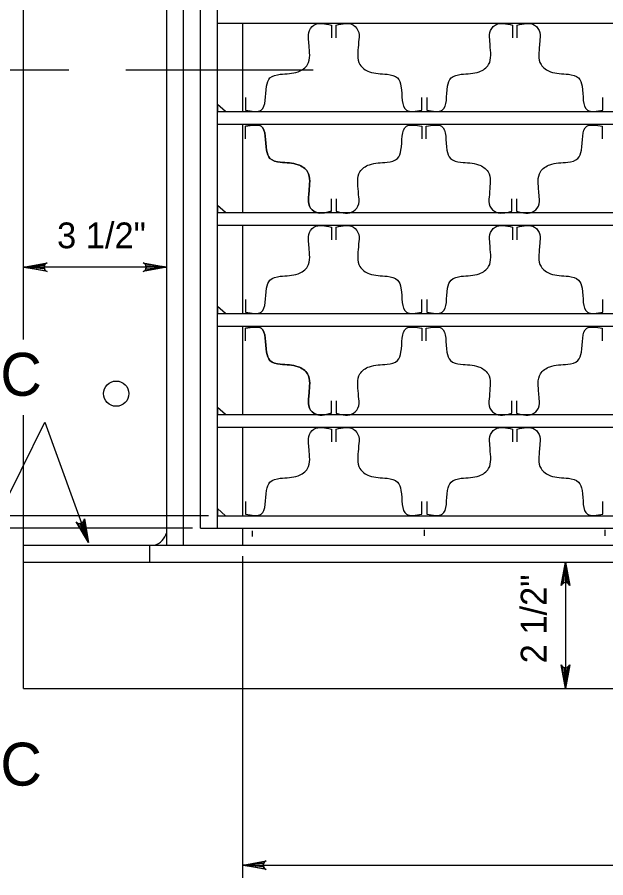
# Model space of a CAD drawing. Extents: x 0.71 to 8.05, y -5.67 to 4.31.
# Drawn here: x 2.185 to 3.555, y 0.105 to 2.109 of the extents above; entities that cross this region are included whole.
import ezdxf

# ---------------------------------------------------------------- set-up
doc = ezdxf.new("R2010")
doc.units = 0
for name, color, linetype in [('DETL-DIMS', 7, 'Continuous'), ('DETL-LINE', 7, 'Continuous'), ('DETL-NOTE', 7, 'Continuous'), ('DETL-TITL', 7, 'Continuous')]:
    doc.layers.add(name, color=color, linetype=linetype)

msp = doc.modelspace()

# ---------------------------------------------------------------- linework, layer by layer
at = {"layer": 'DETL-DIMS'}
for p, q in [((2.0816, 1.9865), (2.3051, 1.9865)), ((2.4374, 1.9865), (2.874, 1.9865)), ((2.5328, 1.527), (2.1992, 1.527)), ((1.8636, 0.3868), (2.2488, 1.1658)), ((2.2488, 1.1658), (2.3502, 0.8858)), ((2.6302, 0.9483), (1.9345, 0.9483)), ((2.5928, 0.9189), (1.7286, 0.9189)), ((2.7098, 0.1048), (2.7098, 0.854)), ((3.4615, 0.8401), (3.4615, 0.546)), ((2.7098, 0.1342), (6.5122, 0.1342))]:
    msp.add_line(p, q, dxfattribs=at)
for points in [[(2.1992, 1.527), (2.2541, 1.5373), (2.2498, 1.5344), (2.2477, 1.5307), (2.247, 1.527), (2.2477, 1.5234), (2.2498, 1.5197), (2.2541, 1.5168), (2.1992, 1.527), (2.2498, 1.5197), (2.2477, 1.5234), (2.1992, 1.527), (2.247, 1.527), (2.2477, 1.5307), (2.1992, 1.527), (2.2498, 1.5344)], [(2.5328, 1.527), (2.4779, 1.5168), (2.4822, 1.5197), (2.4843, 1.5234), (2.485, 1.527), (2.4843, 1.5307), (2.4822, 1.5344), (2.4779, 1.5373), (2.5328, 1.527), (2.4822, 1.5344), (2.4843, 1.5307), (2.5328, 1.527), (2.485, 1.527), (2.4843, 1.5234), (2.5328, 1.527), (2.4822, 1.5197)], [(2.3502, 0.8858), (2.3218, 0.9339), (2.326, 0.9309), (2.3302, 0.9301), (2.3339, 0.9308), (2.3371, 0.9326), (2.3399, 0.9359), (2.3412, 0.9409), (2.3502, 0.8858), (2.3399, 0.9359), (2.3371, 0.9326), (2.3502, 0.8858), (2.3339, 0.9308), (2.3302, 0.9301), (2.3502, 0.8858), (2.326, 0.9309)], [(3.4615, 0.8401), (3.4718, 0.7853), (3.4689, 0.7895), (3.4652, 0.7917), (3.4615, 0.7923), (3.4578, 0.7917), (3.4542, 0.7895), (3.4512, 0.7853), (3.4615, 0.8401), (3.4542, 0.7895), (3.4578, 0.7917), (3.4615, 0.8401), (3.4615, 0.7923), (3.4652, 0.7917), (3.4615, 0.8401), (3.4689, 0.7895)], [(3.4615, 0.546), (3.4512, 0.6008), (3.4542, 0.5966), (3.4578, 0.5944), (3.4615, 0.5938), (3.4652, 0.5944), (3.4689, 0.5966), (3.4718, 0.6008), (3.4615, 0.546), (3.4689, 0.5966), (3.4652, 0.5944), (3.4615, 0.546), (3.4615, 0.5938), (3.4578, 0.5944), (3.4615, 0.546), (3.4542, 0.5966)], [(2.7098, 0.1342), (2.7646, 0.1445), (2.7604, 0.1416), (2.7582, 0.1379), (2.7576, 0.1342), (2.7582, 0.1305), (2.7604, 0.1268), (2.7646, 0.1239), (2.7098, 0.1342), (2.7604, 0.1268), (2.7582, 0.1305), (2.7098, 0.1342), (2.7576, 0.1342), (2.7582, 0.1379), (2.7098, 0.1342), (2.7604, 0.1416)]]:
    msp.add_lwpolyline(points, dxfattribs=at)
at = {"layer": 'DETL-LINE'}
for p, q in [((2.1992, 1.3586), (2.1992, 3.2036)), ((2.5328, 0.8795), (2.5328, 2.8701)), ((2.5722, 0.8795), (2.5722, 2.8701)), ((2.6116, 0.9189), (2.6116, 2.8307)), ((2.651, 0.9189), (2.651, 2.8307)), ((2.651, 2.0954), (6.571, 2.0954)), ((2.7098, 1.8895), (2.7098, 2.0954)), ((2.9162, 2.0909), (2.9162, 2.0615)), ((2.9274, 2.0615), (2.9274, 2.0909)), ((3.338, 2.0909), (3.338, 2.0615)), ((3.3492, 2.0615), (3.3492, 2.0909)), ((2.7166, 1.9223), (2.7166, 1.8928)), ((3.127, 1.8928), (3.127, 1.9223)), ((3.1384, 1.9223), (3.1384, 1.8928)), ((3.5488, 1.8928), (3.5488, 1.9223)), ((2.651, 1.8895), (6.571, 1.8895)), ((2.651, 1.8601), (6.571, 1.8601)), ((2.7098, 1.6542), (2.7098, 1.8601)), ((2.7166, 1.8259), (2.7166, 1.8554)), ((3.127, 1.8554), (3.127, 1.8259)), ((3.1369, 1.8259), (3.1369, 1.8554)), ((3.5473, 1.8554), (3.5473, 1.8259)), ((2.9162, 1.6573), (2.9162, 1.6867)), ((2.9274, 1.6867), (2.9274, 1.6573)), ((3.3365, 1.6573), (3.3365, 1.6867)), ((3.3477, 1.6867), (3.3477, 1.6573)), ((2.651, 1.6542), (6.571, 1.6542)), ((2.651, 1.6248), (6.571, 1.6248)), ((2.7098, 1.4189), (2.7098, 1.6248)), ((2.9162, 1.6203), (2.9162, 1.5909)), ((2.9274, 1.5909), (2.9274, 1.6203)), ((3.338, 1.6203), (3.338, 1.5909)), ((3.3492, 1.5909), (3.3492, 1.6203)), ((2.7166, 1.4517), (2.7166, 1.4222)), ((3.127, 1.4222), (3.127, 1.4517)), ((3.1384, 1.4517), (3.1384, 1.4222)), ((3.5488, 1.4222), (3.5488, 1.4517)), ((2.651, 1.4189), (6.571, 1.4189)), ((2.651, 1.3895), (6.571, 1.3895)), ((2.7098, 1.1836), (2.7098, 1.3895)), ((2.7166, 1.3553), (2.7166, 1.3848)), ((3.127, 1.3848), (3.127, 1.3553)), ((3.1369, 1.3553), (3.1369, 1.3848)), ((3.5473, 1.3848), (3.5473, 1.3553)), ((2.9162, 1.1867), (2.9162, 1.2161)), ((2.9274, 1.2161), (2.9274, 1.1867)), ((3.3365, 1.1867), (3.3365, 1.2161)), ((3.3477, 1.2161), (3.3477, 1.1867)), ((2.651, 1.1836), (6.571, 1.1836)), ((2.1992, 0.546), (2.1992, 1.1826)), ((2.651, 1.1542), (6.571, 1.1542)), ((2.7098, 0.9483), (2.7098, 1.1542)), ((2.9162, 1.1497), (2.9162, 1.1203)), ((2.9274, 1.1203), (2.9274, 1.1497)), ((3.338, 1.1497), (3.338, 1.1203)), ((3.3492, 1.1203), (3.3492, 1.1497)), ((2.7166, 0.9811), (2.7166, 0.9517)), ((3.127, 0.9517), (3.127, 0.9811)), ((3.1384, 0.9811), (3.1384, 0.9517)), ((3.5488, 0.9517), (3.5488, 0.9811)), ((2.651, 0.9483), (6.571, 0.9483)), ((2.6116, 0.9189), (6.6104, 0.9189)), ((2.7098, 0.8795), (2.7098, 0.9189)), ((2.7327, 0.8996), (2.7327, 0.9132)), ((3.1331, 0.9017), (3.1331, 0.9154)), ((3.5537, 0.9017), (3.5537, 0.9154)), ((2.1992, 0.8795), (7.0228, 0.8795)), ((2.4933, 0.8401), (2.4933, 0.8795)), ((2.1992, 0.8401), (7.0228, 0.8401)), ((2.1992, 0.546), (7.0228, 0.546))]:
    msp.add_line(p, q, dxfattribs=at)
for points in [[(2.6695, 1.8895), (2.651, 1.9059), (2.651, 1.8895)], [(2.6695, 1.6542), (2.651, 1.6706), (2.651, 1.6542)], [(2.6695, 1.4189), (2.651, 1.4353), (2.651, 1.4189)], [(2.6695, 1.1836), (2.651, 1.2), (2.651, 1.1836)], [(2.6695, 0.9483), (2.651, 0.9647), (2.651, 0.9483)]]:
    msp.add_lwpolyline(points, close=True, dxfattribs=at)
msp.add_circle((2.4151, 1.2325), 0.0294, dxfattribs=at)
msp.add_arc((2.4933, 0.9189), 0.0407, 284.2782, 345.7218, dxfattribs=at)
for points in [[(2.7166, 1.8928), (2.7526, 1.8928), (2.7652, 1.9485), (2.7733, 1.9678), (2.7971, 1.9765), (2.8389, 1.9824), (2.8608, 1.999), (2.8643, 2.0445), (2.8639, 2.0521), (2.8634, 2.0736), (2.8758, 2.0909), (2.9162, 2.0909)], [(2.9274, 2.0909), (2.9678, 2.0909), (2.9801, 2.0736), (2.9797, 2.0521), (2.9792, 2.0445), (2.9828, 1.999), (3.0047, 1.9824), (3.0465, 1.9765), (3.0703, 1.9678), (3.0784, 1.9485), (3.091, 1.8928), (3.127, 1.8928)], [(3.1384, 1.8928), (3.1744, 1.8928), (3.187, 1.9485), (3.1951, 1.9678), (3.2189, 1.9765), (3.2607, 1.9824), (3.2826, 1.999), (3.2861, 2.0445), (3.2857, 2.0521), (3.2852, 2.0736), (3.2976, 2.0909), (3.338, 2.0909)], [(3.3492, 2.0909), (3.3896, 2.0909), (3.4019, 2.0736), (3.4015, 2.0521), (3.401, 2.0445), (3.4046, 1.999), (3.4265, 1.9824), (3.4683, 1.9765), (3.4921, 1.9678), (3.5002, 1.9485), (3.5128, 1.8928), (3.5488, 1.8928)], [(2.7166, 1.8554), (2.7526, 1.8554), (2.7652, 1.7997), (2.7733, 1.7804), (2.7971, 1.7717), (2.8389, 1.7658), (2.8608, 1.7492), (2.8643, 1.7037), (2.8639, 1.696), (2.8634, 1.6746), (2.8758, 1.6573), (2.9162, 1.6573)], [(2.7166, 1.8554), (2.7526, 1.8554), (2.7652, 1.7997), (2.7733, 1.7804), (2.7971, 1.7717), (2.8389, 1.7658), (2.8608, 1.7492), (2.8643, 1.7037), (2.8639, 1.696), (2.8634, 1.6746), (2.8758, 1.6573), (2.9162, 1.6573)], [(2.9162, 1.6573), (2.8758, 1.6573), (2.8634, 1.6746), (2.8639, 1.696), (2.8643, 1.7037), (2.8608, 1.7492), (2.8389, 1.7658), (2.7971, 1.7717), (2.7733, 1.7804), (2.7652, 1.7997), (2.7526, 1.8554), (2.7166, 1.8554)], [(2.7166, 1.8554), (2.7526, 1.8554), (2.7652, 1.7997), (2.7733, 1.7804), (2.7971, 1.7717), (2.8389, 1.7658), (2.8608, 1.7492), (2.8643, 1.7037), (2.8639, 1.696), (2.8634, 1.6746), (2.8758, 1.6573), (2.9162, 1.6573)], [(2.7166, 1.8554), (2.7526, 1.8554), (2.7652, 1.7997), (2.7733, 1.7804), (2.7971, 1.7717), (2.8389, 1.7658), (2.8608, 1.7492), (2.8643, 1.7037), (2.8639, 1.696), (2.8634, 1.6746), (2.8758, 1.6573), (2.9162, 1.6573)], [(2.9274, 1.6573), (2.9678, 1.6573), (2.9801, 1.6746), (2.9797, 1.696), (2.9792, 1.7037), (2.9828, 1.7492), (3.0047, 1.7658), (3.0465, 1.7717), (3.0703, 1.7804), (3.0784, 1.7997), (3.091, 1.8554), (3.127, 1.8554)], [(2.9274, 1.6573), (2.9678, 1.6573), (2.9801, 1.6746), (2.9797, 1.696), (2.9792, 1.7037), (2.9828, 1.7492), (3.0047, 1.7658), (3.0465, 1.7717), (3.0703, 1.7804), (3.0784, 1.7997), (3.091, 1.8554), (3.127, 1.8554)], [(2.9274, 1.6573), (2.9678, 1.6573), (2.9801, 1.6746), (2.9797, 1.696), (2.9792, 1.7037), (2.9828, 1.7492), (3.0047, 1.7658), (3.0465, 1.7717), (3.0703, 1.7804), (3.0784, 1.7997), (3.091, 1.8554), (3.127, 1.8554)], [(3.1369, 1.8554), (3.1728, 1.8554), (3.1855, 1.7997), (3.1936, 1.7804), (3.2174, 1.7717), (3.2592, 1.7658), (3.2811, 1.7492), (3.2846, 1.7037), (3.2842, 1.696), (3.2837, 1.6746), (3.2961, 1.6573), (3.3365, 1.6573)], [(3.1369, 1.8554), (3.1728, 1.8554), (3.1855, 1.7997), (3.1936, 1.7804), (3.2174, 1.7717), (3.2592, 1.7658), (3.2811, 1.7492), (3.2846, 1.7037), (3.2842, 1.696), (3.2837, 1.6746), (3.2961, 1.6573), (3.3365, 1.6573)], [(3.1369, 1.8554), (3.1728, 1.8554), (3.1855, 1.7997), (3.1936, 1.7804), (3.2174, 1.7717), (3.2592, 1.7658), (3.2811, 1.7492), (3.2846, 1.7037), (3.2842, 1.696), (3.2837, 1.6746), (3.2961, 1.6573), (3.3365, 1.6573)], [(3.3477, 1.6573), (3.3881, 1.6573), (3.4004, 1.6746), (3.4, 1.696), (3.3995, 1.7037), (3.4031, 1.7492), (3.425, 1.7658), (3.4667, 1.7717), (3.4906, 1.7804), (3.4987, 1.7997), (3.5113, 1.8554), (3.5473, 1.8554)], [(3.3477, 1.6573), (3.3881, 1.6573), (3.4004, 1.6746), (3.4, 1.696), (3.3995, 1.7037), (3.4031, 1.7492), (3.425, 1.7658), (3.4667, 1.7717), (3.4906, 1.7804), (3.4987, 1.7997), (3.5113, 1.8554), (3.5473, 1.8554)], [(3.3477, 1.6573), (3.3881, 1.6573), (3.4004, 1.6746), (3.4, 1.696), (3.3995, 1.7037), (3.4031, 1.7492), (3.425, 1.7658), (3.4667, 1.7717), (3.4906, 1.7804), (3.4987, 1.7997), (3.5113, 1.8554), (3.5473, 1.8554)], [(2.7166, 1.4222), (2.7526, 1.4222), (2.7652, 1.4779), (2.7733, 1.4972), (2.7971, 1.5059), (2.8389, 1.5118), (2.8608, 1.5284), (2.8643, 1.5739), (2.8639, 1.5816), (2.8634, 1.603), (2.8758, 1.6203), (2.9162, 1.6203)], [(2.9274, 1.6203), (2.9678, 1.6203), (2.9801, 1.603), (2.9797, 1.5816), (2.9792, 1.5739), (2.9828, 1.5284), (3.0047, 1.5118), (3.0465, 1.5059), (3.0703, 1.4972), (3.0784, 1.4779), (3.091, 1.4222), (3.127, 1.4222)], [(3.1384, 1.4222), (3.1744, 1.4222), (3.187, 1.4779), (3.1951, 1.4972), (3.2189, 1.5059), (3.2607, 1.5118), (3.2826, 1.5284), (3.2861, 1.5739), (3.2857, 1.5816), (3.2852, 1.603), (3.2976, 1.6203), (3.338, 1.6203)], [(3.3492, 1.6203), (3.3896, 1.6203), (3.4019, 1.603), (3.4015, 1.5816), (3.401, 1.5739), (3.4046, 1.5284), (3.4265, 1.5118), (3.4683, 1.5059), (3.4921, 1.4972), (3.5002, 1.4779), (3.5128, 1.4222), (3.5488, 1.4222)], [(2.7166, 1.3848), (2.7526, 1.3848), (2.7652, 1.3291), (2.7733, 1.3098), (2.7971, 1.3011), (2.8389, 1.2952), (2.8608, 1.2786), (2.8643, 1.2331), (2.8639, 1.2255), (2.8634, 1.204), (2.8758, 1.1867), (2.9162, 1.1867)], [(2.7166, 1.3848), (2.7526, 1.3848), (2.7652, 1.3291), (2.7733, 1.3098), (2.7971, 1.3011), (2.8389, 1.2952), (2.8608, 1.2786), (2.8643, 1.2331), (2.8639, 1.2255), (2.8634, 1.204), (2.8758, 1.1867), (2.9162, 1.1867)], [(2.9162, 1.1867), (2.8758, 1.1867), (2.8634, 1.204), (2.8639, 1.2255), (2.8643, 1.2331), (2.8608, 1.2786), (2.8389, 1.2952), (2.7971, 1.3011), (2.7733, 1.3098), (2.7652, 1.3291), (2.7526, 1.3848), (2.7166, 1.3848)], [(2.7166, 1.3848), (2.7526, 1.3848), (2.7652, 1.3291), (2.7733, 1.3098), (2.7971, 1.3011), (2.8389, 1.2952), (2.8608, 1.2786), (2.8643, 1.2331), (2.8639, 1.2255), (2.8634, 1.204), (2.8758, 1.1867), (2.9162, 1.1867)], [(2.7166, 1.3848), (2.7526, 1.3848), (2.7652, 1.3291), (2.7733, 1.3098), (2.7971, 1.3011), (2.8389, 1.2952), (2.8608, 1.2786), (2.8643, 1.2331), (2.8639, 1.2255), (2.8634, 1.204), (2.8758, 1.1867), (2.9162, 1.1867)], [(2.9274, 1.1867), (2.9678, 1.1867), (2.9801, 1.204), (2.9797, 1.2255), (2.9792, 1.2331), (2.9828, 1.2786), (3.0047, 1.2952), (3.0465, 1.3011), (3.0703, 1.3098), (3.0784, 1.3291), (3.091, 1.3848), (3.127, 1.3848)], [(2.9274, 1.1867), (2.9678, 1.1867), (2.9801, 1.204), (2.9797, 1.2255), (2.9792, 1.2331), (2.9828, 1.2786), (3.0047, 1.2952), (3.0465, 1.3011), (3.0703, 1.3098), (3.0784, 1.3291), (3.091, 1.3848), (3.127, 1.3848)], [(2.9274, 1.1867), (2.9678, 1.1867), (2.9801, 1.204), (2.9797, 1.2255), (2.9792, 1.2331), (2.9828, 1.2786), (3.0047, 1.2952), (3.0465, 1.3011), (3.0703, 1.3098), (3.0784, 1.3291), (3.091, 1.3848), (3.127, 1.3848)], [(3.1369, 1.3848), (3.1728, 1.3848), (3.1855, 1.3291), (3.1936, 1.3098), (3.2174, 1.3011), (3.2592, 1.2952), (3.2811, 1.2786), (3.2846, 1.2331), (3.2842, 1.2255), (3.2837, 1.204), (3.2961, 1.1867), (3.3365, 1.1867)], [(3.1369, 1.3848), (3.1728, 1.3848), (3.1855, 1.3291), (3.1936, 1.3098), (3.2174, 1.3011), (3.2592, 1.2952), (3.2811, 1.2786), (3.2846, 1.2331), (3.2842, 1.2255), (3.2837, 1.204), (3.2961, 1.1867), (3.3365, 1.1867)], [(3.1369, 1.3848), (3.1728, 1.3848), (3.1855, 1.3291), (3.1936, 1.3098), (3.2174, 1.3011), (3.2592, 1.2952), (3.2811, 1.2786), (3.2846, 1.2331), (3.2842, 1.2255), (3.2837, 1.204), (3.2961, 1.1867), (3.3365, 1.1867)], [(3.3477, 1.1867), (3.3881, 1.1867), (3.4004, 1.204), (3.4, 1.2255), (3.3995, 1.2331), (3.4031, 1.2786), (3.425, 1.2952), (3.4667, 1.3011), (3.4906, 1.3098), (3.4987, 1.3291), (3.5113, 1.3848), (3.5473, 1.3848)], [(3.3477, 1.1867), (3.3881, 1.1867), (3.4004, 1.204), (3.4, 1.2255), (3.3995, 1.2331), (3.4031, 1.2786), (3.425, 1.2952), (3.4667, 1.3011), (3.4906, 1.3098), (3.4987, 1.3291), (3.5113, 1.3848), (3.5473, 1.3848)], [(3.3477, 1.1867), (3.3881, 1.1867), (3.4004, 1.204), (3.4, 1.2255), (3.3995, 1.2331), (3.4031, 1.2786), (3.425, 1.2952), (3.4667, 1.3011), (3.4906, 1.3098), (3.4987, 1.3291), (3.5113, 1.3848), (3.5473, 1.3848)], [(2.7166, 0.9517), (2.7526, 0.9516), (2.7652, 1.0073), (2.7733, 1.0266), (2.7971, 1.0353), (2.8389, 1.0412), (2.8608, 1.0578), (2.8643, 1.1033), (2.8639, 1.111), (2.8634, 1.1324), (2.8758, 1.1497), (2.9162, 1.1497)], [(2.9274, 1.1497), (2.9678, 1.1497), (2.9801, 1.1324), (2.9797, 1.111), (2.9792, 1.1033), (2.9828, 1.0578), (3.0047, 1.0412), (3.0465, 1.0353), (3.0703, 1.0266), (3.0784, 1.0073), (3.091, 0.9516), (3.127, 0.9517)], [(3.1384, 0.9517), (3.1744, 0.9516), (3.187, 1.0073), (3.1951, 1.0266), (3.2189, 1.0353), (3.2607, 1.0412), (3.2826, 1.0578), (3.2861, 1.1033), (3.2857, 1.111), (3.2852, 1.1324), (3.2976, 1.1497), (3.338, 1.1497)], [(3.3492, 1.1497), (3.3896, 1.1497), (3.4019, 1.1324), (3.4015, 1.111), (3.401, 1.1033), (3.4046, 1.0578), (3.4265, 1.0412), (3.4683, 1.0353), (3.4921, 1.0266), (3.5002, 1.0073), (3.5128, 0.9516), (3.5488, 0.9517)]]:
    msp.add_spline(points, degree=3, dxfattribs=at)

# ---------------------------------------------------------------- texts
at = {"layer": 'DETL-NOTE'}
msp.add_text('3 1/2"', height=0.06, dxfattribs=at).set_placement((2.2773, 1.5712))
msp.add_text('2 1/2"', height=0.06, rotation=90, dxfattribs=at).set_placement((3.4174, 0.6043))
at = {"layer": 'DETL-TITL'}
for p in [(2.1453, 1.2276), (2.1453, 0.3195)]:
    msp.add_text('C', height=0.1, dxfattribs=at).set_placement(p)

doc.saveas('drawing.dxf')
